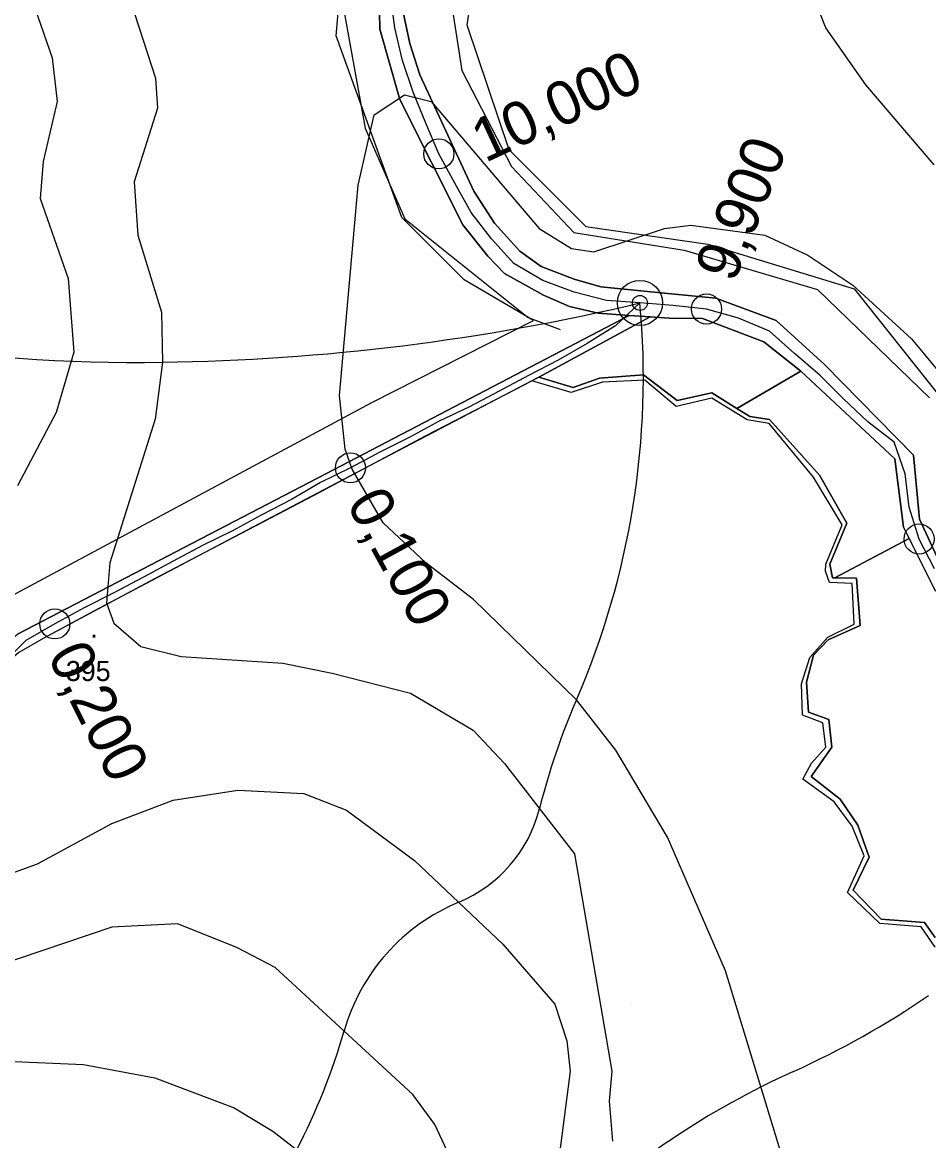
# Model space of a CAD drawing. Extents: x -510989 to -501240, y -1184665 to -1176098.
# Drawn here: x -509533.7 to -509262.7, y -1180896.8 to -1180562.4 of the extents above; entities that cross this region are included whole.
import ezdxf

# ---------------------------------------------------------------- set-up
doc = ezdxf.new("R2010")
doc.units = 0
for name, color, linetype in [('NAVRH_revitalizace_toku', 7, 'Continuous'), ('NAVRH_rozvodnice', 7, 'Continuous'), ('ostatni_plocha_x_neplodna_puda', 7, 'Continuous'), ('popis', 7, 'Continuous'), ('STAV_povodi', 7, 'Continuous'), ('STAV_systematicke_odvodneni', 7, 'Continuous'), ('trasovani_toku', 7, 'Continuous'), ('trvaly_travni_porost', 7, 'Continuous'), ('vodni_plocha_x_vodni_tok_v_koryt_prir_n_upr', 7, 'Continuous'), ('vodni_plocha_x_vodni_tok_v_koryte_umelem', 7, 'Continuous'), ('vrstevnice_01', 7, 'Continuous'), ('vrstevnice_02', 7, 'Continuous'), ('vrstevnice_05', 7, 'Continuous')]:
    doc.layers.add(name, color=color, linetype=linetype)

msp = doc.modelspace()

# ---------------------------------------------------------------- linework, layer by layer
at = {"layer": 'NAVRH_revitalizace_toku'}
for points in [[(-509251.68, -1180051.44), (-509284.55, -1180226.79), (-509300.99, -1180374.75), (-509325.65, -1180421.33), (-509370.86, -1180461.06), (-509421.55, -1180503.53), (-509437.68, -1180558.22), (-509431.14, -1180593.95), (-509419.28, -1180621.11), (-509382.45, -1180650.58), (-509372.86, -1180654.24)], [(-509217.43, -1180056.92), (-509232.5, -1180170.63), (-509254.42, -1180314.47), (-509261.27, -1180377.49), (-509279.08, -1180419.96), (-509306.48, -1180458.32), (-509365.38, -1180499.42), (-509395.55, -1180530.26), (-509400.81, -1180563.08), (-509388.25, -1180600.36), (-509365.16, -1180623.45), (-509328.69, -1180628.72), (-509284.94, -1180642.09), (-509256.17, -1180678.15), (-509235.24, -1180752.86), (-509207.84, -1180777.52)]]:
    msp.add_lwpolyline(points, dxfattribs=at)
at = {"layer": 'NAVRH_rozvodnice'}
for centre, radius, start, end in [((-509498.93, -1180148.82), 515.23, 251.7028, 270.7921), ((-509500.9, -1180006.77), 657.29, 270.79208, 283.361), ((-509590.2, -1180668.57), 242.22, 336.5405, 5.2828), ((-509175.32, -1180848.62), 210.04, 156.5405, 165.9145), ((-509418.96, -1180787.48), 41.15, 292.5147, 345.9145), ((-509380.51, -1180880.24), 59.25, 112.5147, 164.0948), ((-509412.14, -1180634.76), 264.85, 294.3222, 304.362), ((-509618.25, -1180812.49), 187.94, 332.4235, 344.0948), ((-509199.37, -1181105.52), 251.76, 114.3222, 133.3684)]:
    msp.add_arc(centre, radius, start, end, dxfattribs=at)
at = {"layer": 'ostatni_plocha_x_neplodna_puda'}
for points in [[(-509345.91, -1180650.45), (-509340.3, -1180650.85), (-509330.29, -1180650.97), (-509311.95, -1180657.91), (-509300.87, -1180666.66), (-509320.07, -1180677.79), (-509327.53, -1180673.19), (-509337.82, -1180675.47), (-509347.98, -1180667.81), (-509361.09, -1180668.74), (-509369.02, -1180671.6), (-509379.27, -1180668.49)], [(-509300.87, -1180666.66), (-509272.8, -1180692.91), (-509270.17, -1180713.31), (-509268.47, -1180716.7), (-509290.76, -1180728.46), (-509291.44, -1180728.45), (-509292.21, -1180724.39), (-509287.17, -1180712.17), (-509295.34, -1180697.76), (-509310.27, -1180681.11), (-509316.13, -1180680.22), (-509320.07, -1180677.79)]]:
    msp.add_lwpolyline(points, close=True, dxfattribs=at)
msp.add_lwpolyline([(-509260.73, -1180836.05), (-509263.94, -1180831.54), (-509276.86, -1180830.54), (-509285.19, -1180821.89), (-509280.47, -1180811.99), (-509283.84, -1180802.46), (-509289.07, -1180794.71), (-509297.79, -1180787.91), (-509291.58, -1180779.1), (-509292.5, -1180770.84), (-509298.57, -1180768.65), (-509299.18, -1180759.64), (-509297.06, -1180751.6), (-509292.73, -1180747), (-509283.17, -1180742.76), (-509284.27, -1180728.57), (-509290.76, -1180728.46), (-509268.47, -1180716.7), (-509260.57, -1180732.43)], dxfattribs=at)
at = {"layer": 'popis'}
msp.add_lwpolyline([(-509260.74, -1180838.93), (-509264.89, -1180832.82), (-509277.22, -1180831.85), (-509286.91, -1180822.57), (-509281.92, -1180811.63), (-509285.51, -1180802.79), (-509290.91, -1180795.45), (-509300.32, -1180788.66), (-509297.69, -1180783.95), (-509293.39, -1180779.11), (-509294.34, -1180771.81), (-509300.43, -1180769.6), (-509300.71, -1180760.18), (-509298.22, -1180752.29), (-509292.82, -1180746.19), (-509284.92, -1180742.3), (-509285.48, -1180730.18), (-509292.26, -1180729.9), (-509293.51, -1180726.44), (-509293.37, -1180724.36), (-509288.52, -1180712.59), (-509297.1, -1180698.36), (-509310.38, -1180682.29), (-509316.98, -1180681.23), (-509327.5, -1180674.72), (-509338.16, -1180677.21), (-509347.57, -1180669.32), (-509360.17, -1180670.01), (-509369.56, -1180673.06), (-509381.33, -1180669.6), (-509398.3, -1180678.4), (-509429.87, -1180694.98), (-509470.48, -1180716.35), (-509510.89, -1180737.7), (-509527.53, -1180746.61), (-509534.75, -1180750.86)], dxfattribs=at)
at = {"layer": 'STAV_povodi'}
for centre, radius, start, end in [((-509412.14, -1180634.76), 264.85, 294.3222, 304.362), ((-509199.37, -1181105.52), 251.76, 114.3222, 133.3684)]:
    msp.add_arc(centre, radius, start, end, dxfattribs=at)
at = {"layer": 'STAV_systematicke_odvodneni'}
for p, q in [((-509439.85, -1180566.42), (-509436.66, -1180529.7)), ((-509406.03, -1180552.28), (-509402.31, -1180576.76)), ((-509420.17, -1180620.7), (-509439.85, -1180566.42)), ((-509402.31, -1180576.76), (-509387.41, -1180605.5)), ((-509387.41, -1180605.5), (-509368.79, -1180625.19)), ((-509401.55, -1180639.33), (-509420.17, -1180620.7)), ((-509368.79, -1180625.19), (-509335.81, -1180630.51)), ((-509335.81, -1180630.51), (-509295.91, -1180642.22)), ((-509380.8, -1180651.57), (-509401.55, -1180639.33)), ((-509295.91, -1180642.22), (-509262.4, -1180674.69)), ((-509429.21, -1180676.05), (-509380.8, -1180651.57)), ((-509538.27, -1180734.6), (-509429.21, -1180676.05))]:
    msp.add_line(p, q, dxfattribs=at)
at = {"layer": 'trasovani_toku'}
for p, q in [((-509422.31, -1180564), (-509423.61, -1180554.08)), ((-509420.06, -1180573.74), (-509422.31, -1180564)), ((-509416.82, -1180583.2), (-509420.06, -1180573.74)), ((-509413.04, -1180592.46), (-509416.82, -1180583.2)), ((-509409.15, -1180601.67), (-509413.04, -1180592.46)), ((-509404.38, -1180610.46), (-509409.15, -1180601.67)), ((-509399.52, -1180619.2), (-509404.38, -1180610.46)), ((-509393.39, -1180627.1), (-509399.52, -1180619.2)), ((-509386.68, -1180634.52), (-509393.39, -1180627.1)), ((-509378.03, -1180639.53), (-509386.68, -1180634.52)), ((-509368.68, -1180643.07), (-509378.03, -1180639.53)), ((-509358.98, -1180645.5), (-509368.68, -1180643.07)), ((-509349.01, -1180646.27), (-509358.98, -1180645.5)), ((-509349.01, -1180646.27), (-509356.28, -1180653.14)), ((-509339.04, -1180647.05), (-509349.01, -1180646.27)), ((-509329.09, -1180648.09), (-509339.04, -1180647.05)), ((-509319.48, -1180650.84), (-509329.09, -1180648.09)), ((-509310.26, -1180654.73), (-509319.48, -1180650.84)), ((-509356.28, -1180653.14), (-509364.81, -1180658.35)), ((-509302.81, -1180661.39), (-509310.26, -1180654.73)), ((-509364.81, -1180658.35), (-509373.45, -1180663.39)), ((-509295.23, -1180667.91), (-509302.81, -1180661.39)), ((-509373.45, -1180663.39), (-509382.35, -1180667.94)), ((-509382.35, -1180667.94), (-509391.15, -1180672.7)), ((-509288.12, -1180674.95), (-509295.23, -1180667.91)), ((-509391.15, -1180672.7), (-509400.01, -1180677.34)), ((-509280.82, -1180681.78), (-509288.12, -1180674.95)), ((-509400.01, -1180677.34), (-509409.05, -1180681.61)), ((-509409.05, -1180681.61), (-509417.84, -1180686.38)), ((-509272.95, -1180687.95), (-509280.82, -1180681.78)), ((-509417.84, -1180686.38), (-509426.75, -1180690.92)), ((-509269.64, -1180697.39), (-509272.95, -1180687.95)), ((-509426.75, -1180690.92), (-509435.59, -1180695.59)), ((-509435.59, -1180695.59), (-509444.57, -1180699.99)), ((-509268.47, -1180707.32), (-509269.64, -1180697.39)), ((-509444.57, -1180699.99), (-509453.22, -1180705.01)), ((-509453.22, -1180705.01), (-509462.11, -1180709.6)), ((-509265.51, -1180716.87), (-509268.47, -1180707.32)), ((-509462.11, -1180709.6), (-509470.88, -1180714.4)), ((-509470.88, -1180714.4), (-509479.87, -1180718.77)), ((-509479.87, -1180718.77), (-509488.66, -1180723.54)), ((-509260.94, -1180725.77), (-509265.51, -1180716.87)), ((-509488.66, -1180723.54), (-509497.48, -1180728.25)), ((-509497.48, -1180728.25), (-509506.31, -1180732.94)), ((-509506.31, -1180732.94), (-509515.26, -1180737.41)), ((-509515.26, -1180737.41), (-509524.01, -1180742.25)), ((-509524.01, -1180742.25), (-509532.68, -1180747.23)), ((-509532.68, -1180747.23), (-509539.75, -1180754.3))]:
    msp.add_line(p, q, dxfattribs=at)
for centre, radius in [((-509409.15, -1180601.67), 4.5), ((-509349.01, -1180646.27), 6.75), ((-509349.01, -1180646.27), 2.25), ((-509329.09, -1180648.09), 4.5), ((-509435.59, -1180695.59), 4.5), ((-509265.51, -1180716.87), 4.5), ((-509524.01, -1180742.25), 4.5)]:
    msp.add_circle(centre, radius, dxfattribs=at)
at = {"layer": 'trvaly_travni_porost'}
for points in [[(-509427.22, -1180544.4), (-509426.83, -1180564.36), (-509420.81, -1180585.39), (-509402.02, -1180622.88), (-509394.46, -1180632.28), (-509389.49, -1180637.49), (-509377.83, -1180643.94), (-509370.12, -1180647.38), (-509361.45, -1180649.33), (-509352.23, -1180649.99), (-509442.98, -1180697.39), (-509535.2, -1180745.32)], [(-509256.87, -1180729.16), (-509265.37, -1180710.96), (-509267.2, -1180691.77), (-509293.77, -1180664.65), (-509308.22, -1180651.52), (-509326.27, -1180644.8), (-509346.73, -1180642.81), (-509360.72, -1180641.45), (-509368.64, -1180639.14), (-509378.51, -1180635.37), (-509384.95, -1180630.75), (-509392.49, -1180622.45), (-509398.69, -1180612.85), (-509414.82, -1180578.01), (-509417.86, -1180568.68), (-509419.77, -1180559.8)]]:
    msp.add_lwpolyline(points, dxfattribs=at)
at = {"layer": 'vodni_plocha_x_vodni_tok_v_koryt_prir_n_upr'}
msp.add_lwpolyline([(-509352.23, -1180649.99), (-509345.91, -1180650.45), (-509379.27, -1180668.49), (-509381.33, -1180669.6), (-509383.58, -1180670.75), (-509413.02, -1180686.05), (-509446.72, -1180703.91), (-509494.24, -1180728.79), (-509527.53, -1180746.61), (-509534.75, -1180750.86), (-509540.39, -1180755.69), (-509538.63, -1180752.9), (-509538.03, -1180751.95), (-509541.54, -1180750.5), (-509537.66, -1180747.33), (-509535.2, -1180745.32), (-509442.98, -1180697.39)], close=True, dxfattribs=at)
msp.add_lwpolyline([(-509260.74, -1180838.93), (-509264.89, -1180832.82), (-509277.22, -1180831.85), (-509286.91, -1180822.57), (-509281.92, -1180811.63), (-509285.51, -1180802.79), (-509290.91, -1180795.45), (-509300.32, -1180788.66), (-509297.69, -1180783.95), (-509293.39, -1180779.11), (-509294.34, -1180771.81), (-509300.43, -1180769.6), (-509300.71, -1180760.18), (-509298.22, -1180752.29), (-509292.82, -1180746.19), (-509284.92, -1180742.3), (-509285.48, -1180730.18), (-509292.26, -1180729.9), (-509293.51, -1180726.44), (-509293.37, -1180724.36), (-509288.52, -1180712.59), (-509297.1, -1180698.36), (-509310.38, -1180682.29), (-509316.98, -1180681.23), (-509327.5, -1180674.72), (-509338.16, -1180677.21), (-509347.57, -1180669.32), (-509360.17, -1180670.01), (-509369.56, -1180673.06), (-509381.33, -1180669.6), (-509379.27, -1180668.49), (-509369.02, -1180671.6), (-509361.09, -1180668.74), (-509347.98, -1180667.81), (-509337.82, -1180675.47), (-509327.53, -1180673.19), (-509320.07, -1180677.79), (-509316.13, -1180680.22), (-509310.27, -1180681.11), (-509295.34, -1180697.76), (-509287.17, -1180712.17), (-509292.21, -1180724.39), (-509291.44, -1180728.45), (-509290.76, -1180728.46), (-509284.27, -1180728.57), (-509283.17, -1180742.76), (-509292.73, -1180747), (-509297.06, -1180751.6), (-509299.18, -1180759.64), (-509298.57, -1180768.65), (-509292.5, -1180770.84), (-509291.58, -1180779.1), (-509297.79, -1180787.91), (-509289.07, -1180794.71), (-509283.84, -1180802.46), (-509280.47, -1180811.99), (-509285.19, -1180821.89), (-509276.86, -1180830.54), (-509263.94, -1180831.54), (-509260.73, -1180836.05)], dxfattribs=at)
at = {"layer": 'vodni_plocha_x_vodni_tok_v_koryte_umelem'}
for points in [[(-509260.57, -1180732.43), (-509268.47, -1180716.7), (-509270.17, -1180713.31), (-509272.8, -1180692.91), (-509300.87, -1180666.66), (-509311.95, -1180657.91), (-509330.29, -1180650.97), (-509340.3, -1180650.85), (-509345.91, -1180650.45), (-509352.23, -1180649.99), (-509361.45, -1180649.33), (-509370.12, -1180647.38), (-509377.83, -1180643.94), (-509389.49, -1180637.49), (-509394.46, -1180632.28), (-509402.02, -1180622.88), (-509420.81, -1180585.39), (-509426.83, -1180564.36), (-509427.22, -1180544.4)], [(-509419.77, -1180559.8), (-509417.86, -1180568.68), (-509414.82, -1180578.01), (-509398.69, -1180612.85), (-509392.49, -1180622.45), (-509384.95, -1180630.75), (-509378.51, -1180635.37), (-509368.64, -1180639.14), (-509360.72, -1180641.45), (-509346.73, -1180642.81), (-509326.27, -1180644.8), (-509308.22, -1180651.52), (-509293.77, -1180664.65), (-509267.2, -1180691.77), (-509265.37, -1180710.96), (-509256.87, -1180729.16)]]:
    msp.add_lwpolyline(points, dxfattribs=at)
at = {"layer": 'vrstevnice_01'}
for points in [[(-509532.41, -1180551), (-509524.81, -1180573), (-509523.31, -1180586), (-509527.5, -1180604), (-509528.41, -1180615), (-509520, -1180639), (-509518.31, -1180661), (-509523.59, -1180679), (-509535.19, -1180701)], [(-509306.69, -1180901), (-509323.41, -1180846), (-509340.81, -1180806), (-509356.19, -1180780), (-509368, -1180765), (-509398.81, -1180735), (-509413.09, -1180724), (-509425.81, -1180712), (-509435.09, -1180696), (-509437.19, -1180690), (-509438.91, -1180674), (-509433.31, -1180611), (-509428.5, -1180590), (-509419.41, -1180584), (-509411.41, -1180586), (-509379.19, -1180624), (-509369.5, -1180630), (-509362.81, -1180631), (-509341.69, -1180624), (-509333.81, -1180623), (-509311.69, -1180626), (-509298.81, -1180632), (-509285.31, -1180641), (-509267.81, -1180657), (-509253.69, -1180674)], [(-509543.09, -1180819), (-509529.19, -1180814), (-509506.91, -1180802), (-509488.59, -1180795), (-509469.31, -1180792), (-509449.5, -1180793), (-509436.81, -1180798), (-509416.41, -1180813), (-509390, -1180838), (-509374.41, -1180856), (-509370.91, -1180867), (-509369.91, -1180876), (-509373.81, -1180906)], [(-509724.19, -1180906), (-509711.09, -1180889), (-509704.69, -1180885), (-509689.19, -1180881), (-509657.81, -1180888), (-509641, -1180888), (-509572.31, -1180876), (-509538.41, -1180873), (-509515.41, -1180874), (-509494.09, -1180878), (-509470.41, -1180887), (-509458.81, -1180894), (-509444.5, -1180905)]]:
    msp.add_lwpolyline(points, dxfattribs=at)
at = {"layer": 'vrstevnice_02'}
msp.add_line((-509351.5, -1180856), (-509351.5, -1180856), dxfattribs=at)
for points in [[(-509261, -1180605), (-509281.41, -1180581), (-509293.41, -1180564), (-509302.91, -1180540), (-509303.81, -1180530), (-509302.91, -1180508), (-509298.19, -1180484), (-509286.91, -1180457), (-509281.81, -1180449), (-509237.91, -1180386)], [(-509500.09, -1180560), (-509493.91, -1180579), (-509493.31, -1180588), (-509500.31, -1180610), (-509499.19, -1180626), (-509492.09, -1180649), (-509491.81, -1180664), (-509494, -1180681), (-509507.59, -1180724), (-509508.59, -1180736), (-509506.31, -1180742), (-509498.31, -1180749), (-509486.19, -1180752), (-509455.81, -1180754), (-509441.09, -1180757), (-509417.59, -1180763), (-509398.91, -1180774), (-509389.5, -1180784), (-509368.59, -1180811), (-509357.41, -1180876), (-509358.19, -1180885), (-509357.19, -1180897)], [(-509403.81, -1180906), (-509410.31, -1180892), (-509416.91, -1180883), (-509458.09, -1180845), (-509469.59, -1180839), (-509487.31, -1180832), (-509507, -1180833), (-509569.31, -1180854)]]:
    msp.add_lwpolyline(points, dxfattribs=at)

# ---------------------------------------------------------------- texts
at = {"layer": 'trasovani_toku'}
for s, rotation, p in [('10,000', 25.0261, (-509395.34, -1180604.48)), ('9,900', 68.4243, (-509320.84, -1180640.56)), ('0,100', 298.6958, (-509436.99, -1180706.19)), ('0,200', 296.5554, (-509526.39, -1180751.73))]:
    msp.add_text(s, height=13, rotation=rotation, dxfattribs=at).set_placement(p)
at = {"layer": 'vrstevnice_05'}
for s, p in [('.', (-509513.39, -1180746.41)), ('395', (-509520.71, -1180759.35))]:
    msp.add_text(s, height=6, dxfattribs=at).set_placement(p)

doc.saveas('drawing.dxf')
